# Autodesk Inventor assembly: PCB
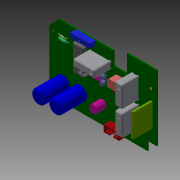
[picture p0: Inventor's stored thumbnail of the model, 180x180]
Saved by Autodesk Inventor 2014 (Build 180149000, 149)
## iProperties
Shininess: 64.0
Length Units: 11272
Angle Units: 11279
Time Units: 11290
Mass Units: 11286
Length Display Precision: 3
Angle Display Precision: 2
Compacted: True
Part Number: PCB
Document SubType Name: Assembly
Created: 2003-04
Designer: t_enrig
Manufacturer: Standard
Standards Organization: Custom
Mass: 60.3399 g
Surface Area: 445.616 cm^2
Volume: 60.3399 cm^3
Density: 1 g/cm^3
Density: 0.0
Volumn: 0.0
Area: 0.0
PropertySet Name: Model Information
Control State: 0
Master: False
Checked Out: False
Author: t_enrig
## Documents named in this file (18)
- C:\Users\iTools\Desktop\tutorial files\Cable and Harness\PCB.iam
- C:\Users\iTools\Desktop\tutorial files\Cable and Harness\RAD1100X390X870P89043.ipt
- C:\Users\iTools\Desktop\tutorial files\Cable and Harness\CPCYLD700X1400P30043.ipt
- C:\Users\iTools\Desktop\tutorial files\Cable and Harness\FIDMARK1.ipt
- C:\Users\iTools\Desktop\tutorial files\Cable and Harness\SMC_1206.ipt
- C:\Users\iTools\Desktop\tutorial files\Cable and Harness\DIP10024W600L1300.ipt
- C:\Users\iTools\Desktop\tutorial files\Cable and Harness\TO220.ipt
- C:\Users\iTools\Desktop\tutorial files\Cable and Harness\example1.ipt
- C:\Users\iTools\Desktop\tutorial files\Cable and Harness\CONP100VHTM1SQW10012K.ipt
- C:\Users\iTools\Desktop\tutorial files\Cable and Harness\SMC_2817P.ipt
- C:\Users\iTools\Desktop\tutorial files\Cable and Harness\DAXD100P40043.ipt
- C:\Users\iTools\Desktop\tutorial files\Cable and Harness\LTP.ipt
- C:\Users\iTools\Desktop\tutorial files\Cable and Harness\DAXD150P50051.ipt
- C:\Users\iTools\Desktop\tutorial files\Cable and Harness\TO237.ipt
- C:\Users\iTools\Desktop\tutorial files\Cable and Harness\CYLD400X500P20031.ipt
- C:\Users\iTools\Desktop\tutorial files\Cable and Harness\BR400X400X400P200X20043.ipt
- C:\Users\iTools\Desktop\tutorial files\Cable and Harness\FIDMARK2.ipt
- C:\Users\iTools\Desktop\tutorial files\Cable and Harness\RC Male Connector.ipt
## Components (25 placed, 17 different names)
1. RAD1100X390X870P89043
2. CPCYLD700X1400P30043
3. FIDMARK1
4. SMC_1206
5. DIP10024W600L1300
6. RAD1100X390X870P89043
7. TO220
8. example1 — Mate:1, Angle:1
9. CONP100VHTM1SQW10012K
10. SMC_1206
11. SMC_2817P
12. DAXD100P40043
13. DAXD150P50051
14. TO237
15. SMC_1206
16. CPCYLD700X1400P30043
17. CYLD400X500P20031
18. RAD1100X390X870P89043
19. BR400X400X400P200X20043
20. SMC_2817P
21. FIDMARK2
22. TO237
23. SMC_1206
24. LTP:1
25. RC Male Connector:1 — Mate:1, Angle:1
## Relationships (2: Mate 1, Angle 1)
- Mate:1: example1 ↔ RC Male Connector:1
- Angle:1: example1 ↔ RC Male Connector:1
